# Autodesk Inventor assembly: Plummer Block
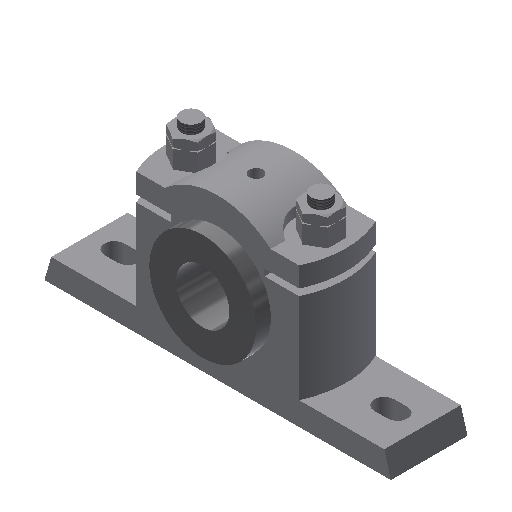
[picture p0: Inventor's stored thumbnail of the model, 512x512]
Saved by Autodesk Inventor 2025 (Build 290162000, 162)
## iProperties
Created: 2011-07
Part Number: Plummer Block
Document SubType Name: Assembly
Designer: CadCim
Author: CadCim
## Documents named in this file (7)
- D:\CAD\Inventor\Autodesk Inventor 2025\Resources\2025\c09_Inv_2025_tut\c09_tut02_inv\Plummer Block\Plummer Block.iam
- D:\CAD\Inventor\Autodesk Inventor 2025\Resources\2025\c09_Inv_2025_tut\c09_tut02_inv\Plummer Block\Casting.ipt
- D:\CAD\Inventor\Autodesk Inventor 2025\Resources\2025\c09_Inv_2025_tut\c09_tut02_inv\Plummer Block\Brasses.ipt
- D:\CAD\Inventor\Autodesk Inventor 2025\Resources\2025\c09_Inv_2025_tut\c09_tut02_inv\Plummer Block\Cap.ipt
- D:\CAD\Inventor\Autodesk Inventor 2025\Resources\2025\c09_Inv_2025_tut\c09_tut02_inv\Plummer Block\Bolt.ipt
- D:\CAD\Inventor\Autodesk Inventor 2025\Resources\2025\c09_Inv_2025_tut\c09_tut02_inv\Plummer Block\Nut.ipt
- D:\CAD\Inventor\Autodesk Inventor 2025\Resources\2025\c09_Inv_2025_tut\c09_tut02_inv\Plummer Block\locknut.ipt
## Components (9 placed, 6 different names)
1. Casting:1 — Mate:1, Mate:2, Insert:1, Angle:1, Insert:2, Angle:2
2. Brasses:1 — Mate:1, Mate:2, Mate:3, Mate:4
3. Cap:1 — Mate:3, Mate:4, Insert:3, Insert:4
4. Bolt:1 — Insert:1, Angle:1
5. Bolt:2 — Insert:2, Angle:2
6. Nut.:4 — Insert:3, Insert:5, Angle:4
7. Nut.:5 — Insert:4, Insert:6, Angle:3
8. locknut:1 — Insert:5, Angle:4
9. locknut:2 — Insert:6, Angle:3
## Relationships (14: Insert 6, Mate 4, Angle 4)
- Mate:1: Casting:1 ↔ Brasses:1
- Mate:2: Casting:1 ↔ Brasses:1
- Mate:3: Brasses:1 ↔ Cap:1
- Mate:4: Brasses:1 ↔ Cap:1
- Insert:1: Casting:1 ↔ Bolt:1
- Angle:1: Casting:1 ↔ Bolt:1
- Insert:2: Casting:1 ↔ Bolt:2
- Angle:2: Casting:1 ↔ Bolt:2
- Insert:3: Cap:1 ↔ Nut.:4
- Insert:4: Cap:1 ↔ Nut.:5
- Insert:5: Nut.:4 ↔ locknut:1
- Insert:6: Nut.:5 ↔ locknut:2
- Angle:3: Nut.:5 ↔ locknut:2
- Angle:4: Nut.:4 ↔ locknut:1
